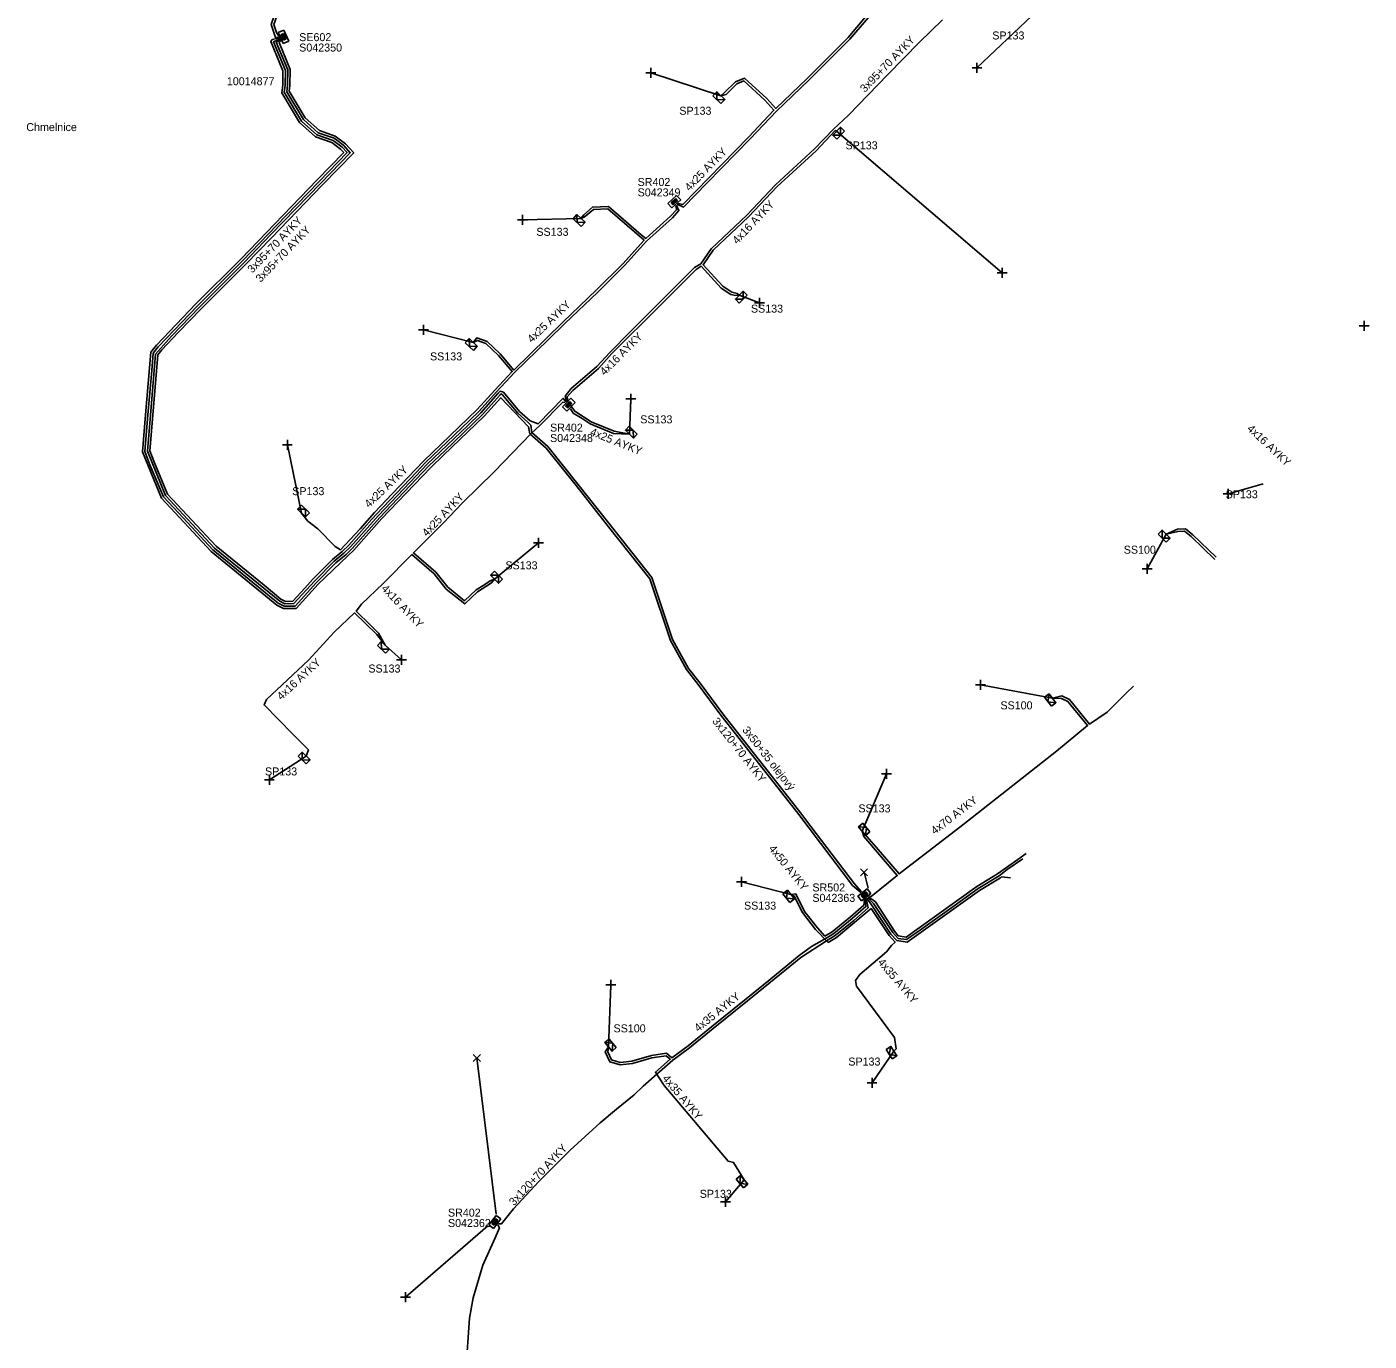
# Model space of a CAD drawing. Extents: x -737417 to -734469, y -1145580 to -1142703.
# Drawn here: x -736657.1 to -736489.4, y -1144452.9 to -1144288.6 of the extents above; entities that cross this region are included whole.
import ezdxf

# ---------------------------------------------------------------- set-up
doc = ezdxf.new("R2010")
doc.units = 0
for name, color, linetype in [('Vrstva 1', 7, 'Continuous'), ('Vrstva 26', 7, 'Continuous'), ('Vrstva 27', 7, 'Continuous'), ('Vrstva 28', 7, 'Continuous'), ('Vrstva 29', 7, 'Continuous'), ('Vrstva 30', 7, 'Continuous'), ('Vrstva 31', 7, 'Continuous'), ('Vrstva 33', 7, 'Continuous'), ('Vrstva 34', 7, 'Continuous'), ('Vrstva 5', 7, 'Continuous'), ('Vrstva 52', 7, 'Continuous'), ('Vrstva 54', 7, 'Continuous'), ('Vrstva 59', 7, 'Continuous'), ('Vrstva 6', 7, 'Continuous'), ('Vrstva 8', 7, 'Continuous'), ('Vrstva 9', 7, 'Continuous')]:
    doc.layers.add(name, color=color, linetype=linetype)

# ---------------------------------------------------------------- blocks, each defined once
blk = doc.blocks.new('NN800')
at = {"layer": 'Vrstva 1'}
for points in [[(-0.44, 0.44), (0.44, -0.44)], [(-0.44, -0.44), (0.44, 0.44)]]:
    blk.add_lwpolyline(points, dxfattribs=at)
blk = doc.blocks.new('NN620')
at = {"layer": 'Vrstva 8'}
for points in [[(0.75, 0), (-0.75, 0)], [(-0.75, 0), (-0.75, -0.75)], [(0.75, -0.75), (0.75, 0)], [(-0.75, -0.75), (0.75, -0.75)], [(0.37, -0.18), (-0.38, -0.18)], [(-0.38, -0.18), (-0.38, -0.56)], [(-0.38, -0.56), (0.37, -0.56)], [(0.32, -0.23), (-0.33, -0.23)], [(-0.33, -0.23), (-0.33, -0.51)], [(-0.33, -0.51), (0.32, -0.51)], [(0.27, -0.27), (-0.28, -0.27)], [(-0.28, -0.27), (-0.28, -0.46)], [(-0.28, -0.46), (0.27, -0.46)], [(0.23, -0.32), (-0.23, -0.32)], [(-0.23, -0.32), (-0.23, -0.42)], [(-0.23, -0.42), (0.23, -0.42)], [(-0.19, -0.37), (0.19, -0.37)], [(0.23, -0.42), (0.23, -0.32)], [(0.27, -0.46), (0.27, -0.27)], [(0.32, -0.51), (0.32, -0.23)], [(0.37, -0.56), (0.37, -0.18)]]:
    blk.add_lwpolyline(points, dxfattribs=at)
blk = doc.blocks.new('NN630')
at = {"layer": 'Vrstva 9'}
for points in [[(0, -0.7), (-0.7, 0)], [(-0.7, -0.7), (-0.7, 0), (0.7, 0), (0.7, -0.7)], [(-0.7, -0.7), (0.7, -0.7)], [(0, -0.7), (0.7, 0)]]:
    blk.add_lwpolyline(points, dxfattribs=at)

msp = doc.modelspace()

# ---------------------------------------------------------------- linework, layer by layer
at = {"layer": 'Vrstva 5'}
for points in [[(-736575.73, -1144310.73), (-736575.15, -1144310.83), (-736566.94, -1144302.42), (-736563.76, -1144299.04), (-736564.88, -1144297.81), (-736567.5, -1144295.4), (-736568.38, -1144295.76), (-736569.74, -1144297.09), (-736570.38, -1144297.25), (-736569.92, -1144296.85), (-736568.54, -1144295.5), (-736567.44, -1144295.06), (-736564.66, -1144297.59), (-736563.53, -1144298.84), (-736559.61, -1144295.08), (-736554.48, -1144289.98), (-736552.32, -1144287.4), (-736555.59, -1144283.76), (-736555.73, -1144283.31)], [(-736625.8, -1144286.04), (-736625.81, -1144286.07), (-736626.57, -1144288.33), (-736626.06, -1144289.96), (-736625.58, -1144289.92)], [(-736625.49, -1144286.03), (-736625.51, -1144286.27), (-736626.25, -1144288.33), (-736625.93, -1144289.37), (-736625.63, -1144289.8)], [(-736589.65, -1144335.42), (-736589.84, -1144334.78), (-736589.11, -1144333.86), (-736585.88, -1144331.11), (-736584.22, -1144329.28), (-736581.76, -1144326.8), (-736573.67, -1144318.74), (-736572.88, -1144318.25), (-736571.59, -1144316.37), (-736567.16, -1144312.16), (-736563.56, -1144308.37), (-736558.7, -1144303.9), (-736556.31, -1144301.41), (-736554.45, -1144299.7), (-736549.53, -1144294.6), (-736545.55, -1144290.55), (-736542.71, -1144287.76)], [(-736575.83, -1144310.82), (-736575.05, -1144311.17), (-736572.08, -1144308.12), (-736566.72, -1144302.62), (-736563.44, -1144299.17), (-736559.41, -1144295.3), (-736554.26, -1144290.18), (-736551.97, -1144287.53)], [(-736625.52, -1144290.03), (-736626.44, -1144290.22), (-736626.62, -1144290.48), (-736625.11, -1144294.14), (-736625.13, -1144295.9), (-736625.24, -1144296.89), (-736623.03, -1144300.61), (-736621.03, -1144302.4), (-736619, -1144303.1), (-736617.91, -1144303.93), (-736617.51, -1144304.36), (-736620.82, -1144307.77), (-736630.39, -1144317.67), (-736635.98, -1144323.26), (-736640.92, -1144328.43), (-736641.63, -1144329.3), (-736642.28, -1144337.12), (-736642.66, -1144341.76), (-736640.3, -1144347.53), (-736634.08, -1144354.22), (-736625.86, -1144360.91), (-736625.03, -1144361.35), (-736623.46, -1144361.32), (-736620.71, -1144358.28), (-736617, -1144354.77), (-736616.24, -1144354.05), (-736612.78, -1144350.15), (-736606.65, -1144343.73), (-736605.04, -1144342.17), (-736599.95, -1144337.3), (-736597.88, -1144334.99), (-736594.43, -1144338.63), (-736594.25, -1144339.5), (-736592.22, -1144341.3), (-736588.48, -1144345.96), (-736584.42, -1144351.11), (-736579.27, -1144357.64), (-736576.7, -1144365.35), (-736574.68, -1144368.98), (-736573.21, -1144370.84), (-736570.38, -1144374.68), (-736566.88, -1144379.12), (-736560.63, -1144387.09), (-736553.92, -1144395.96), (-736552.9, -1144396.84)], [(-736625.47, -1144290.15), (-736626.28, -1144290.52), (-736624.81, -1144294.08), (-736624.83, -1144295.92), (-736624.94, -1144296.82), (-736622.79, -1144300.42), (-736620.87, -1144302.14), (-736618.85, -1144302.83), (-736617.7, -1144303.7), (-736617.1, -1144304.36), (-736620.6, -1144307.98), (-736624.75, -1144312.27), (-736630.17, -1144317.89), (-736635.76, -1144323.47), (-736640.7, -1144328.62), (-736641.34, -1144329.42), (-736641.51, -1144331.6), (-736641.98, -1144337.14), (-736642.36, -1144341.72), (-736641.73, -1144343.37), (-736640.04, -1144347.37), (-736637.59, -1144350), (-736633.88, -1144354), (-736631.38, -1144356.05), (-736625.69, -1144360.66), (-736624.96, -1144361.05), (-736623.6, -1144361.03), (-736620.92, -1144358.07), (-736618.49, -1144355.62), (-736617.23, -1144354.58), (-736616.46, -1144353.84), (-736613, -1144349.95), (-736611.55, -1144348.43), (-736606.86, -1144343.52), (-736604.88, -1144341.62), (-736600.17, -1144337.09), (-736597.98, -1144334.64), (-736597.87, -1144334.52), (-736597.73, -1144334.58), (-736595.77, -1144336.91), (-736594.49, -1144338.05), (-736594.14, -1144338.44), (-736594, -1144339.36), (-736592, -1144341.1), (-736588.24, -1144345.78), (-736584.4, -1144350.66), (-736579.02, -1144357.48), (-736576.42, -1144365.23), (-736574.43, -1144368.82), (-736572.97, -1144370.66), (-736570.14, -1144374.5), (-736566.64, -1144378.94), (-736564.01, -1144382.31), (-736560.39, -1144386.91), (-736559.13, -1144388.58), (-736553.7, -1144395.76), (-736552.81, -1144396.76)], [(-736589.74, -1144335.51), (-736590.11, -1144335.07), (-736593.22, -1144338.26), (-736594.21, -1144337.89), (-736595.55, -1144336.7), (-736597.55, -1144334.32), (-736597.96, -1144334.18), (-736598.2, -1144334.44), (-736600.39, -1144336.88), (-736602.04, -1144338.51), (-736607.07, -1144343.31), (-736609.23, -1144345.56), (-736613.22, -1144349.75), (-736616.68, -1144353.63), (-736617.5, -1144354.42), (-736618.71, -1144355.42), (-736621.14, -1144357.86), (-736623.73, -1144360.73), (-736624.89, -1144360.75), (-736625.52, -1144360.41), (-736628.82, -1144357.72), (-736633.67, -1144353.78), (-736639.79, -1144347.2), (-736642.05, -1144341.67), (-736641.68, -1144337.17), (-736641.05, -1144329.53), (-736639.03, -1144327.3), (-736635.55, -1144323.68), (-736629.96, -1144318.09), (-736626.62, -1144314.61), (-736620.39, -1144308.19), (-736616.69, -1144304.37), (-736617.5, -1144303.48), (-736618.71, -1144302.56), (-736620.72, -1144301.87), (-736622.56, -1144300.23), (-736624.62, -1144296.75), (-736624.53, -1144295.94), (-736624.51, -1144294.02), (-736625.94, -1144290.56), (-736625.42, -1144290.27)], [(-736575.92, -1144310.91), (-736575.62, -1144311.61), (-736576.45, -1144312.52), (-736579.66, -1144315.42), (-736582.43, -1144318.47), (-736585.77, -1144321.79), (-736589.88, -1144325.73), (-736591.98, -1144327.78), (-736596.16, -1144331.86), (-736598.43, -1144334.24), (-736600.6, -1144336.67), (-736601.76, -1144337.81), (-736603.73, -1144339.69), (-736607.28, -1144343.1), (-736608.43, -1144344.31), (-736613.44, -1144349.54), (-736614, -1144350.18), (-736616.89, -1144353.42), (-736617.71, -1144354.21), (-736618.93, -1144355.22), (-736621.36, -1144357.66), (-736622.39, -1144358.79), (-736623.87, -1144360.43), (-736624.81, -1144360.45), (-736625.36, -1144360.16), (-736627.47, -1144358.42), (-736633.47, -1144353.56), (-736639.53, -1144347.04), (-736641.17, -1144343.14), (-736641.75, -1144341.63), (-736641.38, -1144337.19), (-736640.76, -1144329.65), (-736640.25, -1144329.02), (-736638.19, -1144326.86), (-736635.33, -1144323.89), (-736629.74, -1144318.3), (-736626.55, -1144315.02), (-736620.17, -1144308.4), (-736616.27, -1144304.37), (-736617.3, -1144303.26), (-736618.57, -1144302.3), (-736620.56, -1144301.61), (-736622.32, -1144300.03), (-736624.32, -1144296.69), (-736624.23, -1144295.96), (-736624.21, -1144293.96), (-736625.6, -1144290.6), (-736625.36, -1144290.39)], [(-736601.33, -1144328.09), (-736600.87, -1144327.49), (-736599.58, -1144327.96), (-736597.95, -1144329.52), (-736596.24, -1144331.53), (-736590.08, -1144325.51), (-736585.97, -1144321.57), (-736582.65, -1144318.27), (-736579.98, -1144315.31), (-736584.53, -1144311.4), (-736586.32, -1144311.47), (-736587.46, -1144312.42), (-736587.87, -1144312.59), (-736587.53, -1144312.13), (-736586.44, -1144311.17), (-736584.43, -1144311.1), (-736580.34, -1144314.62), (-736579.77, -1144315.09), (-736576.67, -1144312.3), (-736575.94, -1144311.53), (-736576.02, -1144311)], [(-736568.08, -1144322.18), (-736568.55, -1144322.2), (-736569.14, -1144322.08), (-736570.36, -1144321.31), (-736572.83, -1144318.57), (-736573.49, -1144318.98), (-736574.64, -1144320.12), (-736576.23, -1144321.71), (-736578.07, -1144323.56), (-736584, -1144329.48), (-736585.67, -1144331.33), (-736588.89, -1144334.08), (-736589.58, -1144334.87), (-736589.53, -1144335.51), (-736588.65, -1144336.69), (-736586.58, -1144338.01), (-736583.71, -1144339.16), (-736581.82, -1144339.54)], [(-736598.67, -1144357.68), (-736599.2, -1144357.89), (-736600, -1144358.4), (-736600.98, -1144359.02), (-736602.41, -1144360.37), (-736604.49, -1144358.69), (-736606, -1144356.81), (-736608.81, -1144354.38), (-736605.07, -1144350.68), (-736602.67, -1144348.15), (-736598.73, -1144344.24), (-736594.1, -1144339.47), (-736593, -1144338.47), (-736590.14, -1144335.56), (-736589.83, -1144335.6)], [(-736589.18, -1144336.38), (-736588.85, -1144336.91), (-736587.73, -1144337.61), (-736586.72, -1144338.27), (-736583.79, -1144339.46), (-736581.82, -1144339.54)], [(-736514.75, -1144352.04), (-736513.33, -1144351.43), (-736512.34, -1144351.39), (-736511.41, -1144352.12), (-736508.48, -1144354.93)], [(-736508.67, -1144355.21), (-736511.61, -1144352.34), (-736512.44, -1144351.69), (-736513.27, -1144351.73), (-736514.75, -1144352.04)], [(-736612.32, -1144365.93), (-736613.15, -1144364.4), (-736614.15, -1144363.42), (-736615.96, -1144361.66), (-736615.31, -1144360.81), (-736612.59, -1144358.21), (-736609.01, -1144354.6), (-736606.22, -1144357.01), (-736604.71, -1144358.91), (-736602.39, -1144360.77), (-736600.8, -1144359.26), (-736599.04, -1144358.13), (-736598.67, -1144357.68)], [(-736551.83, -1144397.28), (-736551.6, -1144397.32), (-736548.35, -1144394.71), (-736552.53, -1144389.84), (-736552.74, -1144389.15), (-736550.99, -1144391.16), (-736548.12, -1144394.51), (-736540.14, -1144388.39), (-736528.43, -1144379.15), (-736524.57, -1144375.98), (-736527.01, -1144372.97), (-736527.83, -1144372.57), (-736528.95, -1144372.56), (-736527.79, -1144372.27), (-736526.82, -1144372.73), (-736524.33, -1144375.78), (-736522.1, -1144374.28), (-736519.75, -1144371.93), (-736518.81, -1144371.03)], [(-736532.25, -1144391.97), (-736533.26, -1144392.69), (-736535.8, -1144394.49), (-736538.4, -1144396.09), (-736545.61, -1144401.24), (-736547.24, -1144402.4), (-736548.21, -1144402.26), (-736548.67, -1144401.65), (-736551.08, -1144398), (-736551.94, -1144397.36)], [(-736552.14, -1144397.52), (-736551.56, -1144398.37), (-736549.14, -1144402.02), (-736548.38, -1144402.81), (-736547.09, -1144403.03), (-736538.07, -1144396.59), (-736535.45, -1144394.98), (-736535.3, -1144394.86), (-736534.19, -1144394.99)], [(-736598.19, -1144438.26), (-736597.79, -1144438.23), (-736596.32, -1144436.38), (-736593.16, -1144433), (-736589.23, -1144429.05), (-736585.47, -1144425.62), (-736583.41, -1144423.93), (-736581.23, -1144422.12), (-736580.11, -1144421.03), (-736578.37, -1144419.52), (-736576.4, -1144417.79), (-736574.29, -1144416.23), (-736571.33, -1144413.84), (-736567.05, -1144410.35), (-736560.41, -1144404.96), (-736557.2, -1144402.87), (-736556.12, -1144402.22), (-736553.79, -1144400.32), (-736551.98, -1144398.74), (-736552.24, -1144397.6)], [(-736584.44, -1144416.13), (-736584.51, -1144416.74), (-736584.05, -1144417.75), (-736582.97, -1144418.06), (-736581.5, -1144417.89), (-736579.07, -1144417.21), (-736577.16, -1144416.93), (-736576.51, -1144417.48), (-736574.47, -1144415.99), (-736571.51, -1144413.58), (-736567.23, -1144410.11), (-736564.4, -1144407.83), (-736560.59, -1144404.72), (-736559.05, -1144403.56), (-736557.16, -1144402.48), (-736556.29, -1144401.97), (-736553.98, -1144400.09), (-736552.26, -1144398.59), (-736552.34, -1144397.68)], [(-736561.64, -1144397.09), (-736561.01, -1144397), (-736559.92, -1144399.19), (-736558.33, -1144401.24), (-736557.39, -1144402.27), (-736556.47, -1144401.73), (-736554.18, -1144399.86), (-736552.54, -1144398.43), (-736552.44, -1144397.77)], [(-736594.93, -1144489.69), (-736595.02, -1144487.91), (-736595.16, -1144480.95), (-736595.43, -1144467.91), (-736595.62, -1144457.47), (-736595.88, -1144456.88), (-736601.32, -1144457.36), (-736602.06, -1144457.22), (-736602.25, -1144456.63), (-736601.78, -1144450.05), (-736601.32, -1144447.49), (-736600.13, -1144443.42), (-736598.57, -1144440), (-736598.05, -1144438.72), (-736598.27, -1144438.36)]]:
    msp.add_lwpolyline(points, dxfattribs=at)
at = {"layer": 'Vrstva 52'}
for points in [[(-736568.08, -1144322.18), (-736568.34, -1144321.97), (-736569.02, -1144321.8), (-736570.16, -1144321.07), (-736572.61, -1144318.37), (-736571.36, -1144316.57), (-736566.94, -1144312.38), (-736563.34, -1144308.59), (-736558.48, -1144304.12), (-736556.09, -1144301.61), (-736555.92, -1144301.69)], [(-736601.33, -1144328.09), (-736600.81, -1144327.83), (-736599.74, -1144328.22), (-736598.17, -1144329.72), (-736596.46, -1144331.73), (-736598.65, -1144334.04), (-736600.82, -1144336.47), (-736604.26, -1144339.74), (-736607.5, -1144342.88), (-736611.45, -1144347), (-736613.66, -1144349.34), (-736615.47, -1144351.4), (-736617.91, -1144353.99), (-736618.6, -1144353.59), (-736620.73, -1144351.38), (-736621.98, -1144350.44), (-736622.79, -1144349.41)], [(-736612.32, -1144365.93), (-736613.39, -1144364.6), (-736616.18, -1144361.88), (-736618.71, -1144364.29), (-736621.93, -1144367.81), (-736627.16, -1144372.71), (-736627.47, -1144373.38), (-736623.88, -1144377.04), (-736621.93, -1144379.02), (-736622.22, -1144379.78)], [(-736552.04, -1144397.44), (-736551.32, -1144398.19), (-736550.07, -1144400.08), (-736548.9, -1144401.84), (-736548.25, -1144402.56), (-736547.17, -1144402.71), (-736545.44, -1144401.49), (-736541.24, -1144398.5), (-736538.23, -1144396.34), (-736535.62, -1144394.73), (-736534.61, -1144393.97), (-736532.66, -1144392.61)], [(-736561.64, -1144397.09), (-736561.21, -1144397.28), (-736560.18, -1144399.35), (-736558.57, -1144401.44), (-736556.97, -1144403.07), (-736555.95, -1144402.47), (-736552.59, -1144399.68), (-736551.62, -1144398.84), (-736549.37, -1144402.21), (-736548.59, -1144403.02), (-736549.07, -1144403.46), (-736549.67, -1144404.23), (-736553.03, -1144407.08), (-736553.58, -1144407.84), (-736553.44, -1144408.55), (-736548.69, -1144414.94), (-736548.47, -1144416.38), (-736548.76, -1144416.65)], [(-736584.44, -1144416.13), (-736584.83, -1144416.76), (-736584.27, -1144418.01), (-736582.99, -1144418.36), (-736581.44, -1144418.19), (-736579.01, -1144417.51), (-736577.24, -1144417.25), (-736576.71, -1144417.67), (-736578.57, -1144419.3), (-736577.47, -1144420.95), (-736569.49, -1144430.41), (-736568.79, -1144430.56), (-736567.48, -1144432.74)]]:
    msp.add_lwpolyline(points, dxfattribs=at)
at = {"layer": 'Vrstva 59'}
for points in [[(-736531.54, -1144287.25), (-736538.38, -1144293.75)], [(-736570.38, -1144297.25), (-736579.13, -1144294.38)], [(-736555.92, -1144301.69), (-736535.25, -1144319.38)], [(-736587.87, -1144312.59), (-736595.19, -1144312.75)], [(-736568.08, -1144322.18), (-736565.56, -1144323.13)], [(-736601.33, -1144328.09), (-736607.56, -1144326.5)], [(-736489.88, -1144325.92), (-736490, -1144326)], [(-736581.82, -1144339.54), (-736581.63, -1144335.13)], [(-736622.79, -1144349.41), (-736624.56, -1144340.88)], [(-736502.6, -1144345.76), (-736507, -1144347)], [(-736514.75, -1144352.04), (-736517.13, -1144356.38)], [(-736598.67, -1144357.68), (-736593.19, -1144353.13)], [(-736612.32, -1144365.93), (-736610.31, -1144367.75)], [(-736528.95, -1144372.56), (-736537.94, -1144370.88)], [(-736622.22, -1144379.78), (-736626.81, -1144382.75)], [(-736552.74, -1144389.15), (-736549.69, -1144382)], [(-736551.98, -1144396.31), (-736552.49, -1144394.3)], [(-736561.64, -1144397.09), (-736567.81, -1144395.5)], [(-736584.44, -1144416.13), (-736584.13, -1144408.38)], [(-736598.48, -1144437.02), (-736600.88, -1144417.5)], [(-736548.76, -1144416.65), (-736551.5, -1144420.63)], [(-736567.48, -1144432.74), (-736569.81, -1144435.5)], [(-736599.5, -1144438.5), (-736609.8, -1144447.4)]]:
    msp.add_lwpolyline(points, dxfattribs=at)

# ---------------------------------------------------------------- block references
at = {"layer": 'Vrstva 28'}
for p, rotation in [((-736625.38, -1144290.04), 114.4644110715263), ((-736575.96, -1144310.77), -137.27408898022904), ((-736589.65, -1144335.6), 45.20804446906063), ((-736552.22, -1144397.42), -141.34019170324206), ((-736598.33, -1144438.23), -127.0025277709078)]:
    msp.add_blockref('NN620', p, dxfattribs=dict(at, rotation=rotation))
at = {"layer": 'Vrstva 31'}
for p, rotation in [((-736570.38, -1144297.25), -44.735966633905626), ((-736555.92, -1144301.69), 45.25521390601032), ((-736587.87, -1144312.59), -42.927716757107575), ((-736568.08, -1144322.18), 44.950733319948), ((-736601.33, -1144328.09), -43.298086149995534), ((-736581.82, -1144339.54), 135.66241953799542), ((-736622.79, -1144349.41), 135.52697784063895), ((-736514.75, -1144352.04), -44.92818887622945), ((-736598.67, -1144357.68), 134.48019433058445), ((-736612.32, -1144365.93), -43.36605845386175), ((-736528.95, -1144372.56), -52.7706167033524), ((-736622.22, -1144379.78), -43.52371662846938), ((-736552.74, -1144389.15), 128.65980829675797), ((-736561.64, -1144397.09), -51.28521665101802), ((-736584.44, -1144416.13), 130.45896385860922), ((-736548.76, -1144416.65), -57.2818444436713), ((-736567.48, -1144432.74), -50.60112777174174)]:
    msp.add_blockref('NN630', p, dxfattribs=dict(at, rotation=rotation))
at = {"layer": 'Vrstva 34'}
for p, rotation in [((-736538.38, -1144293.75), 45), ((-736579.13, -1144294.38), 45), ((-736595.19, -1144312.75), 44.99999995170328), ((-736535.25, -1144319.38), 45), ((-736565.56, -1144323.13), 45), ((-736490, -1144326), 45), ((-736607.56, -1144326.5), 45), ((-736581.63, -1144335.13), 45), ((-736624.56, -1144340.88), 45), ((-736507, -1144347), 45), ((-736593.19, -1144353.13), 44.99999995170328), ((-736517.13, -1144356.38), 45), ((-736610.31, -1144367.75), 45), ((-736537.94, -1144370.88), 44.99999995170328), ((-736626.81, -1144382.75), 45), ((-736549.69, -1144382), 44.99999995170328), ((-736567.81, -1144395.5), 45), ((-736584.13, -1144408.38), 45), ((-736551.5, -1144420.63), 45), ((-736569.81, -1144435.5), 45), ((-736609.8, -1144447.4), 45)]:
    msp.add_blockref('NN800', p, dxfattribs=dict(at, rotation=rotation))
for p in [(-736552.49, -1144394.3), (-736600.88, -1144417.5)]:
    msp.add_blockref('NN800', p, dxfattribs=at)

# ---------------------------------------------------------------- texts
at = {"layer": 'Vrstva 26'}
msp.add_text('10014877', height=1, dxfattribs=at).set_placement((-736632.12, -1144295.94))
at = {"layer": 'Vrstva 27'}
msp.add_text('Chmelnice', height=1, dxfattribs=at).set_placement((-736657.18, -1144301.67))
at = {"layer": 'Vrstva 29'}
for s, p in [('S042350', (-736623.08, -1144291.73)), ('S042349', (-736580.79, -1144309.83)), ('S042348', (-736591.73, -1144340.53)), ('S042363', (-736558.95, -1144398)), ('S042362', (-736604.49, -1144438.64))]:
    msp.add_text(s, height=1, dxfattribs=at).set_placement(p)
at = {"layer": 'Vrstva 30'}
for s, p in [('SE602', (-736623.08, -1144290.43)), ('SR402', (-736580.79, -1144308.53)), ('SR402', (-736591.73, -1144339.23)), ('SR502', (-736558.95, -1144396.7)), ('SR402', (-736604.49, -1144437.34))]:
    msp.add_text(s, height=1, dxfattribs=at).set_placement(p)
at = {"layer": 'Vrstva 33'}
for s, p in [('SP133', (-736536.47, -1144290.22)), ('SP133', (-736575.58, -1144299.63)), ('SP133', (-736554.81, -1144303.95)), ('SS133', (-736593.44, -1144314.76)), ('SS133', (-736566.63, -1144324.36)), ('SS133', (-736606.73, -1144330.33)), ('SS133', (-736580.46, -1144338.2)), ('SP133', (-736623.95, -1144347.17)), ('SP133', (-736507.31, -1144347.56)), ('SS100', (-736520.04, -1144354.49)), ('SS133', (-736597.31, -1144356.44)), ('SS133', (-736614.44, -1144369.34)), ('SS100', (-736535.45, -1144373.94)), ('SP133', (-736627.35, -1144382.2)), ('SS133', (-736553.2, -1144386.82)), ('SS133', (-736567.49, -1144398.97)), ('SS100', (-736583.8, -1144414.31)), ('SP133', (-736554.46, -1144418.46)), ('SP133', (-736573.03, -1144434.99))]:
    msp.add_text(s, height=1, dxfattribs=at).set_placement(p)
at = {"layer": 'Vrstva 54'}
for s, rotation, p in [('4x16 AYKY', 46.473, (-736568.34, -1144315.87)), ('4x16 AYKY', 316.807, (-736504.71, -1144338.97)), ('4x25 AYKY', 43.567, (-736614.36, -1144348.82)), ('4x16 AYKY', 42.709, (-736625.32, -1144372.85)), ('4x35 AYKY', 310.305, (-736550.85, -1144405.59)), ('4x35 AYKY', 310.149, (-736577.77, -1144420.12))]:
    msp.add_text(s, height=1, rotation=rotation, dxfattribs=at).set_placement(p)
at = {"layer": 'Vrstva 6'}
for s, rotation, p in [('3x95+70 AYKY', 46.029, (-736552.39, -1144296.91)), ('4x25 AYKY', 45.717, (-736574.31, -1144309.24)), ('3x95+70 AYKY', 46, (-736628.94, -1144319.49)), ('3x95+70 AYKY', 45.997, (-736627.91, -1144320.65)), ('4x25 AYKY', 43.79, (-736594.01, -1144328.2)), ('4x16 AYKY', 44.976, (-736584.92, -1144332.28)), ('4x25 AYKY', 338.02, (-736586.82, -1144339.63)), ('4x25 AYKY', 46.51, (-736607.12, -1144352.42)), ('4x16 AYKY', 313.708, (-736612.89, -1144358.92)), ('3x120+70 AYKY', 308.244, (-736571.53, -1144375.44)), ('3x50+35 olejový', 307.965, (-736567.77, -1144376.54)), ('4x70 AYKY', 37.486, (-736543.66, -1144389.64)), ('4x50 AYKY', 309.127, (-736564.47, -1144391.39)), ('4x35 AYKY', 39.07, (-736573.21, -1144414.31)), ('3x120+70 AYKY', 46.927, (-736596.24, -1144436.05))]:
    msp.add_text(s, height=1, rotation=rotation, dxfattribs=at).set_placement(p)

doc.saveas('drawing.dxf')
